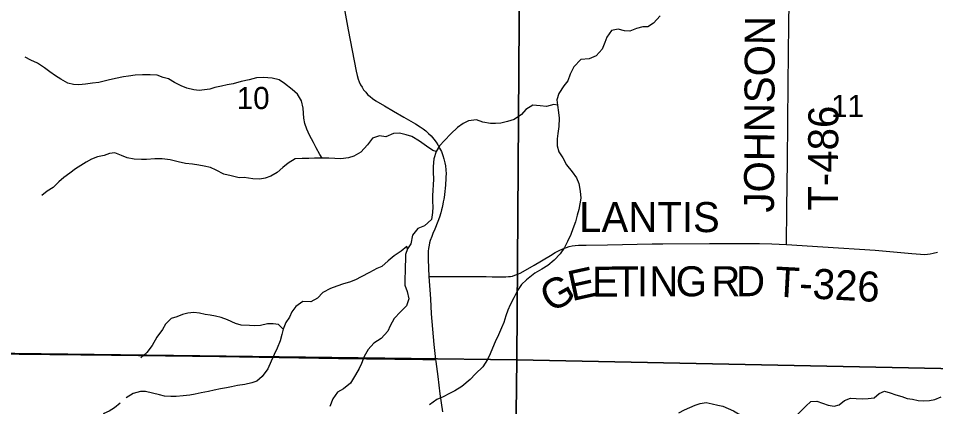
# Model space of a CAD drawing. Extents: x 0 to 34, y 0 to 22.
# Drawn here: x 6.524 to 8.26, y 16.139 to 16.874 of the extents above; entities that cross this region are included whole.
import ezdxf

# ---------------------------------------------------------------- set-up
doc = ezdxf.new("R2010")
doc.units = 0
for name, color, linetype in [('GM_X_Corporation', 7, 'Continuous'), ('GM_X_County_Road', 7, 'Continuous'), ('GM_X_Minor_River', 7, 'Continuous'), ('GM_X_Section_Text', 7, 'Continuous'), ('GM_X_State_Route', 7, 'Continuous'), ('GM_X_Township_Road', 7, 'Continuous'), ('GM_X_Township_Road_Text', 7, 'Continuous')]:
    doc.layers.add(name, color=color, linetype=linetype)

msp = doc.modelspace()

# ---------------------------------------------------------------- linework, layer by layer
at = {"layer": 'GM_X_Corporation'}
for points in [[(7.4742, 17.2327), (7.4675, 16.2282), (6.4674, 16.2404), (6.4721, 17.2442)], [(8.489, 17.2189), (8.4859, 16.2068), (7.4675, 16.2282), (7.4742, 17.2327)], [(6.4674, 16.2404), (7.4675, 16.2282), (7.4535, 15.1233), (6.4527, 15.1394)], [(7.4675, 16.2282), (8.4859, 16.2068), (8.4718, 15.1496), (7.4535, 15.1233)]]:
    msp.add_lwpolyline(points, close=True, dxfattribs=at)
at = {"layer": 'GM_X_County_Road'}
msp.add_lwpolyline([(5.9637, 16.2448), (6.198, 16.2422), (6.4665, 16.239), (6.7005, 16.2366), (6.9049, 16.2341), (7.1297, 16.2306), (7.2895, 16.2286), (7.3138, 16.2288)], dxfattribs=at)
at = {"layer": 'GM_X_Minor_River'}
for points in [[(7.7383, 16.8786), (7.7258, 16.8645), (7.7154, 16.8576), (7.7059, 16.8574), (7.6941, 16.8543), (7.681, 16.8497), (7.6712, 16.8503), (7.6588, 16.8533), (7.6466, 16.8509), (7.6375, 16.8379), (7.6338, 16.8281), (7.629, 16.8157), (7.6177, 16.8027), (7.6043, 16.7973), (7.5883, 16.7958), (7.5751, 16.7821), (7.5686, 16.7682), (7.5641, 16.7555), (7.5563, 16.7458)], [(7.0989, 16.6095), (7.0945, 16.616), (7.0876, 16.6287), (7.0826, 16.6391), (7.0753, 16.6525), (7.0699, 16.6644), (7.066, 16.6751), (7.0647, 16.6846), (7.0638, 16.6941), (7.0633, 16.7036), (7.0599, 16.7177), (7.0522, 16.7301), (7.0426, 16.7394), (7.0277, 16.7504), (7.0176, 16.7571), (7.0048, 16.7608), (6.9882, 16.762), (6.9749, 16.7612), (6.9607, 16.7573), (6.9459, 16.7543), (6.9306, 16.7501), (6.9192, 16.7481), (6.9089, 16.7453), (6.8963, 16.7426), (6.8863, 16.7398), (6.8764, 16.7385), (6.8662, 16.7373), (6.8563, 16.7383), (6.8428, 16.7416), (6.8323, 16.7461), (6.8195, 16.7524), (6.8083, 16.7592), (6.7985, 16.7621), (6.7869, 16.7661), (6.7736, 16.7668), (6.7592, 16.7668), (6.7451, 16.766), (6.7326, 16.7641), (6.7231, 16.7628), (6.7082, 16.7597), (6.6945, 16.7566), (6.6765, 16.7525), (6.6644, 16.7509), (6.6514, 16.749), (6.6385, 16.7478), (6.6286, 16.7484), (6.6177, 16.7509), (6.6046, 16.7589), (6.5945, 16.7648), (6.5837, 16.7726), (6.5737, 16.7801), (6.5606, 16.7891), (6.5482, 16.7947), (6.537, 16.8)], [(7.5563, 16.7458), (7.5469, 16.7316), (7.5432, 16.7196), (7.5444, 16.7097), (7.5463, 16.6956), (7.5476, 16.6846), (7.5468, 16.6694), (7.545, 16.6562), (7.5436, 16.6456), (7.5436, 16.6327), (7.5468, 16.6212), (7.5544, 16.6097), (7.5613, 16.5966), (7.572, 16.5835), (7.5804, 16.5719), (7.5847, 16.5611), (7.5874, 16.5467), (7.5882, 16.5334), (7.5868, 16.5228), (7.585, 16.5122), (7.5817, 16.5013), (7.5784, 16.4889), (7.5731, 16.4757), (7.5698, 16.4652), (7.563, 16.4517), (7.5574, 16.4401), (7.5492, 16.4285), (7.5379, 16.4163), (7.5262, 16.4063), (7.5147, 16.3994), (7.5012, 16.3918), (7.4857, 16.3792), (7.476, 16.3704), (7.4689, 16.3592), (7.4614, 16.3453), (7.455, 16.3318), (7.4506, 16.3217), (7.4465, 16.3108), (7.4428, 16.2988), (7.4383, 16.2882), (7.4327, 16.2751), (7.4267, 16.262), (7.4211, 16.25), (7.417, 16.2391), (7.4118, 16.2286), (7.4031, 16.2148), (7.3895, 16.2014), (7.3794, 16.1907), (7.3635, 16.1774), (7.3504, 16.1694), (7.3397, 16.164), (7.3281, 16.1582), (7.3159, 16.1528), (7.302, 16.1429)], [(7.5444, 16.7097), (7.5376, 16.7106), (7.5235, 16.7071), (7.5114, 16.7082), (7.4974, 16.7097), (7.4847, 16.7013), (7.4765, 16.6916), (7.4626, 16.6821), (7.45, 16.6786), (7.437, 16.6755), (7.4271, 16.675), (7.4173, 16.6749), (7.4033, 16.6775), (7.3913, 16.6819), (7.376, 16.6797), (7.3657, 16.675), (7.3552, 16.6673), (7.3424, 16.6554), (7.3307, 16.6425), (7.321, 16.6328), (7.315, 16.622), (7.3105, 16.6077), (7.309, 16.5937), (7.3091, 16.5827), (7.3096, 16.5694), (7.3093, 16.5588), (7.3083, 16.5486), (7.308, 16.538), (7.3081, 16.5273), (7.3083, 16.5175), (7.308, 16.5065), (7.3058, 16.4933), (7.2929, 16.4811), (7.2799, 16.4761), (7.2701, 16.4634), (7.2667, 16.4472), (7.2608, 16.4375), (7.2567, 16.427), (7.2559, 16.3951), (7.2552, 16.3826), (7.2556, 16.3693), (7.2599, 16.3571), (7.263, 16.3434), (7.2585, 16.3298), (7.2472, 16.3187), (7.2351, 16.3061), (7.2279, 16.2919), (7.2231, 16.2818), (7.211, 16.268), (7.1968, 16.2593), (7.1862, 16.2474), (7.1783, 16.2339), (7.1734, 16.2211), (7.169, 16.2114), (7.1623, 16.1998), (7.1528, 16.1837), (7.1392, 16.1731), (7.1281, 16.1665), (7.1191, 16.1542), (7.1138, 16.1399)], [(7.315, 16.622), (7.3086, 16.6237), (7.2963, 16.6319), (7.2833, 16.6417), (7.2687, 16.6504), (7.2582, 16.6533), (7.2457, 16.6567), (7.234, 16.6558), (7.2194, 16.6497), (7.2073, 16.6512), (7.1943, 16.6469), (7.1849, 16.6347), (7.172, 16.6209), (7.1589, 16.6129), (7.1486, 16.6098), (7.1341, 16.6078), (7.1232, 16.6085), (7.1118, 16.6091), (7.0989, 16.6095), (7.0845, 16.609), (7.0739, 16.6089), (7.061, 16.6085), (7.0477, 16.6081), (7.0349, 16.5996), (7.0245, 16.5915), (7.0137, 16.5823), (7.0021, 16.5754), (6.991, 16.5715), (6.9811, 16.5695), (6.9682, 16.5702), (6.9516, 16.5725), (6.9421, 16.5723), (6.927, 16.5761), (6.9131, 16.5791), (6.8984, 16.5863), (6.8876, 16.5919), (6.8759, 16.5944), (6.8657, 16.5958), (6.8536, 16.598), (6.8404, 16.5991), (6.8268, 16.6021), (6.8113, 16.6063), (6.7966, 16.6078), (6.7825, 16.6077), (6.767, 16.6066), (6.7575, 16.6068), (6.7435, 16.6075), (6.7303, 16.6101), (6.7197, 16.6142), (6.7066, 16.6191), (6.6967, 16.6182), (6.6864, 16.6146), (6.6742, 16.6115), (6.6627, 16.6072), (6.6527, 16.6018), (6.6423, 16.5956), (6.6326, 16.589), (6.6214, 16.5806), (6.6106, 16.5729), (6.6009, 16.5644), (6.5904, 16.554), (6.5785, 16.5467), (6.5684, 16.5386)], [(7.2608, 16.4375), (7.259, 16.4421), (7.2485, 16.4332), (7.2354, 16.4244), (7.2238, 16.4149), (7.2118, 16.4045), (7.2022, 16.4006), (7.1887, 16.3933), (7.173, 16.385), (7.1622, 16.3792), (7.1511, 16.3749), (7.1396, 16.3718), (7.127, 16.3675), (7.1148, 16.3629), (7.1002, 16.3553), (7.09, 16.3442), (7.0774, 16.3377), (7.0626, 16.3384), (7.0494, 16.3285), (7.0416, 16.3188), (7.0372, 16.3083), (7.0305, 16.2982), (7.0256, 16.2862), (7.0227, 16.2757), (7.0198, 16.2636), (7.0141, 16.2497), (7.0081, 16.2381), (7.0025, 16.2253), (6.9964, 16.2111), (6.9855, 16.1965), (6.9757, 16.1873), (6.9658, 16.1841), (6.9528, 16.181), (6.9391, 16.1791), (6.9273, 16.1771), (6.9178, 16.1747), (6.9067, 16.1731), (6.8949, 16.1707), (6.8842, 16.1679), (6.8701, 16.1652), (6.8587, 16.1629), (6.8488, 16.1608), (6.8362, 16.1596), (6.8229, 16.1588), (6.8127, 16.1587), (6.801, 16.1593), (6.7911, 16.1615), (6.7783, 16.1648), (6.7651, 16.1678), (6.7556, 16.1677), (6.7412, 16.1642), (6.728, 16.1558)], [(7.0256, 16.2862), (7.0167, 16.2948), (7.0065, 16.2958), (6.9959, 16.2957), (6.9826, 16.293), (6.9712, 16.2925), (6.9617, 16.2927), (6.9458, 16.2935), (6.9352, 16.2968), (6.9202, 16.3036), (6.9082, 16.3077), (6.8973, 16.3102), (6.8875, 16.3123), (6.8776, 16.3137), (6.8671, 16.3159), (6.8561, 16.3173), (6.8447, 16.3164), (6.8348, 16.3136), (6.8244, 16.3093), (6.8133, 16.3062), (6.8028, 16.2951), (6.7969, 16.285), (6.7863, 16.2705), (6.7772, 16.2551), (6.7674, 16.2417), (6.7561, 16.2317)], [(7.9973, 16.1233), (8.0139, 16.14), (8.0239, 16.1493), (8.0349, 16.1495), (8.0564, 16.1419), (8.0678, 16.1401), (8.0773, 16.143), (8.0873, 16.1508), (8.0984, 16.1555), (8.1094, 16.1549), (8.1208, 16.1543), (8.1322, 16.1545), (8.1432, 16.1562), (8.1532, 16.1644), (8.1628, 16.1687), (8.1737, 16.1655), (8.1847, 16.1619), (8.196, 16.1583), (8.2058, 16.155), (8.216, 16.1533), (8.227, 16.1512), (8.2372, 16.1503), (8.2482, 16.1508), (8.2585, 16.1529), (8.27, 16.158)], [(6.7172, 16.146), (6.706, 16.1372), (6.6959, 16.131), (6.6859, 16.1264), (6.6792, 16.1167), (6.6766, 16.1046), (6.6721, 16.0948), (6.6619, 16.0841), (6.6519, 16.0775), (6.6415, 16.0714), (6.6295, 16.0653), (6.618, 16.0591), (6.6076, 16.0526), (6.5982, 16.0422), (6.5926, 16.0321), (6.5842, 16.0198), (6.5783, 16.0097), (6.5704, 15.9997), (6.5583, 15.9897), (6.5475, 15.9821), (6.5351, 15.9737), (6.5244, 15.9687), (6.5132, 15.9633)], [(7.7737, 16.1277), (7.7846, 16.1332), (7.7945, 16.1376), (7.8045, 16.1424), (7.8144, 16.1452), (7.8258, 16.1469), (7.8368, 16.1448), (7.8474, 16.1423), (7.8572, 16.1402), (7.8674, 16.1359), (7.8771, 16.1315), (7.8869, 16.1257), (7.8888, 16.1253)]]:
    msp.add_lwpolyline(points, dxfattribs=at)
at = {"layer": 'GM_X_State_Route'}
msp.add_lwpolyline([(7.0926, 17.158), (7.1481, 16.8518), (7.1631, 16.7737), (7.1651, 16.7653), (7.1671, 16.7588), (7.1691, 16.7537), (7.1718, 16.7482), (7.1745, 16.7434), (7.1776, 16.7388), (7.1814, 16.734), (7.1851, 16.7299), (7.1896, 16.7257), (7.1945, 16.722), (7.2006, 16.7179), (7.2171, 16.7081), (7.2342, 16.6981), (7.2536, 16.6871), (7.2755, 16.6742), (7.2845, 16.6687), (7.2902, 16.6647), (7.2951, 16.6608), (7.3002, 16.6561), (7.305, 16.6512), (7.3103, 16.645), (7.3145, 16.6396), (7.3179, 16.6343), (7.3213, 16.6283), (7.3246, 16.6216), (7.3274, 16.6146), (7.3295, 16.608), (7.3312, 16.6007), (7.3322, 16.5945), (7.333, 16.587), (7.3334, 16.5795), (7.3333, 16.5742), (7.3331, 16.5677), (7.3326, 16.5621), (7.3323, 16.5584), (7.3318, 16.5528), (7.3311, 16.5461), (7.3303, 16.5406), (7.3296, 16.535), (7.3291, 16.5319), (7.3283, 16.527), (7.3274, 16.5221), (7.3261, 16.516), (7.325, 16.5118), (7.3234, 16.5058), (7.3208, 16.4974), (7.3178, 16.4892), (7.312, 16.4748), (7.3087, 16.4668), (7.3065, 16.461), (7.3037, 16.4535), (7.3024, 16.4494), (7.3013, 16.4447), (7.3002, 16.4385), (7.2996, 16.4331), (7.2994, 16.4282), (7.2996, 16.4177), (7.3009, 16.3858), (7.3038, 16.343), (7.3055, 16.3151), (7.3076, 16.286), (7.3105, 16.2568), (7.3138, 16.2288), (7.3142, 16.225), (7.3177, 16.1966), (7.3218, 16.1634), (7.3265, 16.1296)], dxfattribs=at)
at = {"layer": 'GM_X_Township_Road'}
for points in [[(7.9774, 16.446), (7.9784, 16.5138), (7.9793, 16.6039), (7.9805, 16.7499), (7.9819, 16.8635), (7.983, 16.9405)], [(7.3009, 16.3858), (7.3686, 16.3852), (7.3969, 16.3854), (7.4094, 16.3854), (7.4206, 16.3851), (7.4385, 16.3846), (7.4465, 16.3847), (7.4514, 16.3852), (7.4551, 16.3855), (7.459, 16.3863), (7.4639, 16.3878), (7.469, 16.3897), (7.4752, 16.3926), (7.4999, 16.4068), (7.5308, 16.4253), (7.54, 16.4306), (7.5472, 16.4344), (7.5545, 16.4379), (7.5613, 16.4405), (7.5667, 16.4422), (7.5719, 16.4434), (7.578, 16.4441), (7.5843, 16.4447), (7.5905, 16.4448), (7.5986, 16.4449), (7.639, 16.4452), (7.7233, 16.4472), (7.7438, 16.4473), (7.8318, 16.4479), (7.9263, 16.448), (7.9499, 16.4474), (7.9774, 16.446), (8.0466, 16.4419), (8.1456, 16.4352), (8.1938, 16.4311), (8.2149, 16.4291), (8.2309, 16.4277), (8.2383, 16.4274), (8.2442, 16.4276), (8.2493, 16.4281), (8.2553, 16.4293), (8.263, 16.4315)]]:
    msp.add_lwpolyline(points, dxfattribs=at)

# ---------------------------------------------------------------- texts
at = {"layer": 'GM_X_Section_Text'}
for s, p in [('10', (6.9374, 16.7021)), ('11', (8.062, 16.6871))]:
    msp.add_text(s, height=0.04186, rotation=0, dxfattribs=at).set_placement(p)
at = {"layer": 'GM_X_Township_Road_Text'}
for s, height, rotation, p in [('JOHNSON', 0.05682, 89.6986, (7.9538, 16.5063)), ('T-486', 0.05682, 89.7193, (8.0748, 16.5099)), ('LANTIS', 0.05682, 0, (7.5853, 16.4694)), ('E', 0.0568, 12.4161, (7.5714, 16.3387)), ('E', 0.0568, 0.1457, (7.6097, 16.3475)), ('T', 0.0568, 0.1329, (7.6522, 16.3476)), ('I', 0.0568, 0.1335, (7.6947, 16.3477)), ('N', 0.0568, 0.1293, (7.7181, 16.3478)), ('G', 0.0568, 0.1295, (7.7681, 16.3479)), ('R', 0.0568, 0.1308, (7.8356, 16.3481)), ('D', 0.0568, 0.1313, (7.8822, 16.3482)), ('T-326', 0.05682, 356.9433, (7.9543, 16.3477)), ('G', 0.0568, 29.2336, (7.5319, 16.3159))]:
    msp.add_text(s, height=height, rotation=rotation, dxfattribs=at).set_placement(p)

doc.saveas('drawing.dxf')
